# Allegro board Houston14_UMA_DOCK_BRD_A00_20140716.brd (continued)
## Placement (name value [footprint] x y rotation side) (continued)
LI6  DLW21HN900HQ2L_4P  [MURAT_DLW21HN900HQ2L_4P]  305 83.04 0 bottom
LI7  DLW21HN900HQ2L_4P  [MURAT_DLW21HN900HQ2L_4P]  302.97 78.47 0 bottom
LI8  DLW21HN900HQ2L_4P  [MURAT_DLW21HN900HQ2L_4P]  221.88 101.69 90 bottom
LI9  DLW21HN900HQ2L_4P  [MURAT_DLW21HN900HQ2L_4P]  220.1 101.69 90 bottom
LL1  4.7UH_BRC2012T4R7MD_20%  [TAIYO_BRC2012T4R7MD_2P]  271.48 85.41 180 top
LV1  BLM15BB221SN1D_2P  [MURAT_BLM15BB221SN1D_2P]  91.54 98.3 270 bottom
LV3  DLW21HN900HQ2L_4P  [MURAT_DLW21HN900HQ2L_4P]  94.65 107.1 90 top
LV6  DLW21HN900HQ2L_4P  [MURAT_DLW21HN900HQ2L_4P]  86.58 106.26 90 top
LV9  DLW21HN900HQ2L_4P  [MURAT_DLW21HN900HQ2L_4P]  92.02 106.24 90 top
LV12  DLW21HN900HQ2L_4P  [MURAT_DLW21HN900HQ2L_4P]  89.06 107.17 90 top
LV16  BLM15BB470SN1D_2P  [MURAT_BLM15BB470SN1D_2P]  254.29 106.63 90 top
LV17  BLM15BB470SN1D_2P  [MURAT_BLM15BB470SN1D_2P]  258.1 106.63 90 top
LV18  BLM15BB470SN1D_2P  [MURAT_BLM15BB470SN1D_2P]  260.64 106.63 90 top
LV19  BLM15AG121SN1D_L0402_2P  [MURAT_BLM15AG121SN1D_L0402_2P]  264.96 110.39 90 top
LV20  BLM15AG121SN1D_L0402_2P  [MURAT_BLM15AG121SN1D_L0402_2P]  267.25 110.39 90 top
LV22  BLM15PX181SN1D_2P  [MURAT_BLM15PX181SN1D_2P]  153.67 83.78 90 top
LV23  BLM15PX181SN1D_2P  [MURAT_BLM15PX181SN1D_2P]  150.62 83.78 90 top
LV24  BLM15PX181SN1D_2P  [MURAT_BLM15PX181SN1D_2P]  149.55 101.16 0 top
LV25  BLM15PX181SN1D_2P  [MURAT_BLM15PX181SN1D_2P]  169.3 87.24 0 top
LV27  DLW21HN900HQ2L_4P  [MURAT_DLW21HN900HQ2L_4P]  103.82 93.52 0 bottom
LZ1  DLW21HN900HQ2L_4P  [MURAT_DLW21HN900HQ2L_4P]  94.21 96.5 90 bottom
MIC1  SPM1437HM4H-6_6P  [KNOW_SPM1437HM4H-6_6P]  247.88 113.47 270 top
NOREF  -  []  107.65 115.8 0 top
NOREF#2  -  []  157.2 27.94 0 top
NOREF#3  -  []  7.45 98.25 0 top
NOREF#4  -  []  131.35 119.42 0 top
NOREF#5  -  []  114.27 39.75 0 top
NOREF#6  -  []  221.65 115.8 0 top
NOREF#7  -  []  179 47.52 0 top
NOREF#8  -  []  319.3 27 0 top
NOREF#9  -  []  198.22 119.33 0 top
NOREF#10  -  []  237.55 3 0 top
NOREF#11  -  []  283.05 111.64 0 top
NOREF#12  -  []  179 71.32 0 top
NOREF#13  -  []  94.53 12.89 0 top
NOREF#14  -  []  246.48 92.85 0 top
NOREF#15  -  []  85.15 60.4 0 top
NOREF#16  -  []  103.35 -30.1 0 top
NOREF#17  -  []  257.65 29.8 0 top
NOREF#18  -  []  18.5 80.8 0 top
NOREF#19  -  []  158.65 1.5 0 top
NOREF#20  -  []  117.7 47.52 0 top
NOREF#21  -  []  55.05 115.3 0 top
NOREF#22  -  []  117.7 71.32 0 top
NOREF#23  -  []  18.5 80.8 0 top
NOREF#24  -  []  182.09 22.32 0 top
NOREF#25  -  []  59.65 3.15 0 top
NOREF#26  -  []  279.1 74.41 0 top
NOREF#27  -  []  156.12 19.2 0 top
NOREF#28  -  []  170.8 34.69 180 bottom
NOREF#29  -  []  190.93 24.73 180 bottom
NOREF#30  -  []  249.94 46.87 90 bottom
NOREF#31  -  []  181.79 32.65 180 bottom
NOREF#32  -  []  245.29 44.02 180 bottom
PBATT1  DEREN_40-42251-01001RHF  [DEREN_40-42251-01001RHF_10P-T]  77.6 15.08 214.6 bottom
PC1  1U_0603_10V4Z  [C_0603]  308.34 73.31 270 top
PC3  2200P_0402_50V7K  [C_0402]  72.27 11.24 225 top
PC4  1500P_0402_50V7K  [C_0402]  88.05 3.7 270 top
PC5  0.022U_0805_50V7K  [C_0805]  55.41 88.37 90 bottom
PC9  1000P_0603_50V7K  [C_0603]  44.27 86.82 270 bottom
PC10  10U_0805_25V6K  [C_0805]  58.55 94.55 180 bottom
PC20  0.1U_0402_25V6  [C_0402]  54.84 99.29 0 bottom
PC21  10U_0805_25V6K  [C_0805]  45.81 86.76 270 bottom
PC22  10U_0805_25V6K  [C_0805]  53.28 94.25 0 bottom
PC100  4.7U_0603_10V6K  [C_0603]  220 62.87 90 bottom
PC101  10U_0805_25V6K  [C_0805]  208.74 67.12 0 top
PC102  10U_0805_25V6K  [C_0805]  208.74 67.12 0 bottom
PC105  2200P_0402_50V7K  [C_0402]  208.88 65.6 0 top
PC106  0.1U_0402_25V6  [C_0402]  208.85 64.7 0 top
PC109  0.1U_0603_25V7K  [C_0603]  218.73 67.19 90 top
PC110  0.1U_0603_25V7K  [C_0603]  219.06 58.69 90 top
PC111  680P_0603_50V7K  [C_0603]  213.91 70.23 270 top
PC113  220U_6.3V_M  [C_APXK6R3ARA221MF451]  216.7 76.76 270 bottom
PC114  680P_0603_50V7K  [C_0603]  213.94 60.12 90 top
PC115  220U_6.3V_M  [C_APXK6R3ARA221MF451]  216.19 54.75 90 bottom
PC117  0.1U_0603_25V7K  [C_0603]  215.11 64.58 180 top
PC118  4.7U_0603_10V6K  [C_0603]  216.9 64.26 270 bottom
PC119  1U_0603_10V6K  [C_0603]  221.96 66.98 0 top
PC200  10U_0805_25V6K  [C_0805]  244.26 34.95 270 top
PC201  10U_0805_25V6K  [C_0805]  246.04 34.95 270 top
PC203  2200P_0402_50V7K  [C_0402]  242.86 34.69 270 top
PC204  0.22U_0603_16V7K  [C_0603]  253.97 34.99 0 bottom
PC205  22U_0805_6.3V6M  [C_0805]  257.34 40.62 90 bottom
PC206  0.1U_0402_25V6  [C_0402]  241.96 34.69 270 top
PC207  220U_D2_2VY_R17M  [C_D2]  243.99 35.84 270 bottom
PC208  680P_0603_50V7K  [C_0603]  246.61 29.02 180 top
PC209  1U_0603_10V6K  [C_0603]  263.08 32.62 180 bottom
PC211  1U_0603_10V6K  [C_0603]  261.67 33.85 0 bottom
PC212  0.033U_0402_16V7K  [C_0402]  258.99 40.5 90 bottom
PC213  100P_0402_50V8J  [C_0402]  260.97 40.45 180 bottom
PC214  .1U_0402_16V7K  [C_0402]  260.01 42.53 90 bottom
PC215  .1U_0402_16V7K  [C_0402]  262.34 36.01 0 bottom
PC300  2200P_0402_50V7K  [C_0402]  216.98 52.12 180 bottom
PC301  680P_0603_50V7K  [C_0603]  214.16 52.58 270 bottom
PC302  0.1U_0603_25V7K  [C_0603]  218.29 47.97 180 top
PC303  10U_0805_25V6K  [C_0805]  217.68 50.82 180 bottom
PC304  330P_0402_50V7K  [C_0402]  217.26 44.52 0 bottom
PC305  47U_0805_6.3V6M  [C_0805]  203.49 51.03 90 bottom
PC306  47U_0805_6.3V6M  [C_0805]  205.27 51.03 90 bottom
PC307  22U_0805_6.3VAM  [C_0805]  205.27 51.03 90 top
PC308  22U_0805_6.3VAM  [C_0805]  203.49 51.03 90 top
PC309  4.7U_0603_6.3V6K  [C_0603]  219.49 44.45 270 bottom
PC310  4.7U_0603_6.3V6K  [C_0603]  218.8 47.06 0 bottom
PC311  0.1U_0402_25V6  [C_0402]  219.67 48.82 0 bottom
PC400  1U_0402_6.3V6K  [C_0402]  230.42 60.06 90 bottom
PC401  4.7U_0805_6.3V6K  [C_0805]  228.64 60.18 90 bottom
PC402  .1U_0402_16V7K  [C_0402]  232.45 60.06 90 bottom
PC403  0.01U_0402_25V7K  [C_0402]  230.72 50.87 0 bottom
PC404  22U_0805_6.3V6M  [C_0805]  228.94 50.94 270 bottom
PC500  4700P_0603_50V7K  [C_0603]  105.96 76.2 270 bottom
PC501  .1U_0402_16V7K  [C_0402]  107.23 75.05 90 bottom
PC502  0.068U_0402_16V7K  [C_0402]  109 71.49 90 bottom
PC503  1000P_0402_50V7K  [C_0402]  122.47 90.16 90 top
PC504  0.1U_0402_25V6  [C_0402]  130.85 94 270 bottom
PC505  1U_0603_10V6K  [C_0603]  99.16 67.63 0 bottom
PC506  100P_0402_50V8J  [C_0402]  109 67.33 270 bottom
PC507  0.33U_0603_10V7K  [C_0603]  107.73 64.65 90 bottom
PC508  680P_0603_50V7K  [C_0603]  121.07 86.49 90 top
PC509  1U_0603_10V7K  [C_0603]  129.39 87.82 0 top
PC510  1U_0603_10V7K  [C_0603]  106.46 64.65 90 bottom
PC511  0.1U_0402_25V6  [C_0402]  99.86 65.14 90 bottom
PC512  1500P_0402_50V7K  [C_0402]  111.75 65.34 180 bottom
PC513  0.068U_0402_16V7K  [C_0402]  110.02 71.49 90 bottom
PC514  47P_0402_50V8J  [C_0402]  106.29 64.71 180 top
PC515  10U_0805_25V6K  [C_0805]  125.64 91.34 270 top
PC516  10U_0805_25V6K  [C_0805]  125.64 91.34 270 bottom
PC517  10U_0805_25V6K  [C_0805]  123.86 91.34 270 bottom
PC518  10U_0805_25V6K  [C_0805]  123.86 91.34 270 top
PC519  100U_D_20VM_R55M  [C_D]  120.31 93.35 270 bottom
PC520  2200P_0402_50V7K  [C_0402]  121.58 91.07 270 top
PC521  0.1U_0402_25V6  [C_0402]  126.96 91.35 270 top
PC700  0.1U_0603_25V7K  [C_0603]  63.03 90.17 270 top
PC701  1U_0603_25V6K  [C_0603]  80.75 81.09 180 top
PC702  0.1U_0402_25V6  [C_0402]  79.34 82.24 0 top
PC703  0.1U_0402_25V6  [C_0402]  81.19 83.07 270 top
PC704  10U_0805_25V6K  [C_0805]  94.53 78.64 270 top
PC705  10U_0805_25V6K  [C_0805]  96.3 78.64 270 top
PC706  10U_0805_25V6K  [C_0805]  96.3 78.64 270 bottom
PC707  10U_0805_25V6K  [C_0805]  94.53 78.64 270 bottom
PC708  22U_0805_25V6M  [C_0805]  98.08 78.64 270 top
PC709  10U_0805_25V6K  [C_0805]  82.75 80.46 0 top
PC710  1U_0603_10V6K  [C_0603]  82.63 75.95 0 top
PC711  0.1U_0402_25V6  [C_0402]  79.03 79.39 270 bottom
PC712  0.047U_0603_25V7K~D  [C_0603]  84.3 78.96 180 top
PC713  2200P_0402_50V7K  [C_0402]  80.95 85.4 90 bottom
PC714  22U_0805_25V6M  [C_0805]  82.33 84.39 90 bottom
PC715  22U_0805_25V6M  [C_0805]  84.05 84.38 90 top
PC716  22U_0805_25V6M  [C_0805]  82.33 84.39 90 top
PC717  22U_0805_25V6M  [C_0805]  84.05 84.38 90 bottom
PC718  100P_0402_50V8J  [C_0402]  75.98 78.48 90 bottom
PC719  100P_0402_50V8J  [C_0402]  73.49 79.19 0 top
PC721  1000P_0603_50V7K  [C_0603]  89.79 89.96 270 bottom
PC722  0.1U_0603_25V7K  [C_0603]  113.83 83.95 90 top
PC723  10U_0805_25V6K  [C_0805]  114.08 84.05 90 bottom
PC724  10U_0805_25V6K  [C_0805]  112.05 84.05 90 top
PC725  10U_0805_25V6K  [C_0805]  112.05 84.05 90 bottom
PC726  0.1U_0402_25V6  [C_0402]  82.33 71.11 90 bottom
PC727  0.1U_0402_25V6  [C_0402]  82.28 73.6 180 bottom
PC728  0.1U_0402_25V6  [C_0402]  81.32 72.02 270 bottom
PC729  1U_0603_25V6K  [C_0603]  79.16 72.14 270 bottom
PC732  0.1U_0402_25V6  [C_0402]  80.06 85.54 90 bottom
PC737  100P_0402_50V8J  [C_0402]  74.41 75.14 180 top
PC741  100P_0402_50V8J  [C_0402]  76.9 73.85 180 top
PC805  0.1U_0402_10V7K  [C_0402]  68.99 81.93 180 bottom
PC807  0.47U_0805_25V6K  [C_0805]  117.3 98.19 0 top
PC809  1500P_0402_50V7K  [C_0402]  133.64 103.77 270 top
PC810  0.1U_0402_10V7K  [C_0402]  93.38 71.62 90 top
PC813  0.1U_0603_50V4Z  [C_0603]  99.35 61.98 90 bottom
PC815  0.1U_0603_25V7K  [C_0603]  100.57 62 90 bottom
PC816  0.047U_0603_25V7M  [C_0603]  107.29 59.12 0 bottom
PC817  0.1U_0402_25V4Z~D  [C_0402]  107.21 58.08 0 bottom
PC900  22U_0805_6.3V6M  [C_0805]  148.02 77.26 90 bottom
PC901  22U_0805_6.3V6M  [C_0805]  143.23 77.21 90 bottom
PC902  22U_0805_6.3V6M  [C_0805]  140.5 77.19 90 bottom
PC903  22U_0805_6.3V6M  [C_0805]  137.96 77.19 90 bottom
PC904  22U_0805_6.3V6M  [C_0805]  132.88 77.19 90 bottom
PC913  22U_0805_6.3V6M  [C_0805]  145.85 77.21 90 bottom
PC914  22U_0805_6.3V6M  [C_0805]  135.45 77.16 90 bottom
PC915  2.2U_0805_10V6K  [C_0805]  138.04 77.33 90 top
PC916  2.2U_0805_10V6K  [C_0805]  143.4 77.33 90 top
PC917  22U_0805_6.3V6M  [C_0805]  140.5 77.33 90 top
PC966  220U 2.5V Y D2 ESR9M H1.9 SX  [C_D2]  133.68 81.8 0 bottom
PD1  -  [TVNST52302AB0_SOT523-3]  74.23 7.9 225 top
PD2  -  [TVNST52302AB0_SOT523-3]  72.72 6.43 225 top
PD3  BAS40CW SOT-323  [BAS40-05W_SC70-3]  309.45 72.61 90 top
PD4  SDMK0340L-7-F_SOD323-2~D  [RB751V-40_SOD323-2]  71.11 4.94 270 top
PD5  -  [AZC199-02SPR7G_SOT23-3]  57.43 82.27 270 bottom
PD702  SDMK0340L-7-F_SOD323-2~D  [SDMK0340L-7-F_SOD323-2]  94.6 61.79 0 top
PD704  SDMK0340L-7-F_SOD323-2~D  [SDMK0340L-7-F_SOD323-2]  94.6 60.06 0 top
PD705  SDMK0340L-7-F_SOD323-2~D  [SDMK0340L-7-F_SOD323-2]  94.6 58.31 0 top
PD800  -  [PDS5100H-13_POWERDI5-3]  110.67 80.58 0 top
PD808  -  [PDS5100H-13_POWERDI5-3]  118.42 103 0 bottom
PD813  SDMK0340L-7-F_SOD323-2~D  [SDMK0340L-7-F_SOD323-2]  133.7 101.29 180 top
PD815  -  [BAT54CW_SOT323-3]  54.76 94.81 90 top
PD817  -  [BAT54CW_SOT323-3]  95.78 70.85 0 bottom
PH500  100K_0402_1%_NCP15WF104F03RC  [R_0402]  131.86 90.44 270 bottom
PH501  10K_0402_1%_TSM0A103F34D1RZ  [R_0402]  123.18 75.89 180 bottom
PJP1  PAD-OPEN 1x3m  [JUMP_43X118]  40.73 86.67 270 bottom
PJP4  PAD-OPEN1x1m  [JUMP_43X39]  294.42 38.06 270 bottom
PJP5  PAD-OPEN1x1m  [JUMP_43X39]  294.47 33.17 180 bottom
PJP6  PAD-OPEN1x2m  [JUMP_43X79]  26.97 98.01 0 bottom
PJP7  PAD-OPEN1x1m  [JUMP_43X39]  304.93 49.05 0 top
PJP9  PAD-OPEN1X2m  [JUMP_43X79]  35.66 83.59 270 bottom
PJP10  PAD-OPEN1x1m  [JUMP_43X39]  33.3 94.62 180 bottom
PJP11  PAD-OPEN1x1m  [JUMP_43X39]  195.36 55.49 90 top
PJP12  PAD-OPEN1x1m  [JUMP_43X39]  277.91 56.5 90 top
PJP13  PAD-OPEN1x2m  [JUMP_43X79]  273.41 75.25 90 top
PJP14  PAD-OPEN1x1m  [JUMP_43X39]  245.07 85.79 0 top
PJP15  PAD-OPEN1x1m  [JUMP_43X39]  245.45 64.07 0 top
PJP16  PAD-OPEN1x1m  [JUMP_43X39]  237.22 31.82 180 top
PJP17  PAD-OPEN1x1m  [JUMP_43X39]  271.31 56.5 90 top
PJP18  PAD-OPEN1x3m  [JUMP_43X118]  183.64 79.82 0 top
PJP20  PAD-OPEN1x1m  [JUMP_43X39]  188.95 38.98 90 top
PJP21  PAD-OPEN1x3m  [JUMP_43X118]  212.13 93.45 270 top
PJP22  PAD-OPEN1x3m  [JUMP_43X118]  221.65 92.35 90 top
PJP23  PAD-OPEN1x1m  [JUMP_43X39]  156.32 39.82 180 top
PJP24  PAD-OPEN1x1m  [JUMP_43X39]  150.71 79.9 90 top
PJP25  PAD-OPEN1x1m  [JUMP_43X39]  173.72 88.97 180 top
PJP26  PAD-OPEN1x2m  [JUMP_43X79]  307.34 53.78 90 top
PJP29  PAD-OPEN1x1m  [JUMP_43X39]  85.38 98.06 270 top
PJP32  PAD-OPEN1x1m  [JUMP_43X39]  266.41 77.78 270 top
PJP35  PAD-OPEN1x1m  [JUMP_43X39]  168.4 78.23 270 top
PJP36  PAD-OPEN1x3m  [JUMP_43X118]  177.11 85.99 90 top
PJP100  PAD-OPEN 1x3m  [JUMP_43X118]  203.82 69.04 270 bottom
PJP101  PAD-OPEN 1x3m  [JUMP_43X118]  220.98 55.95 0 bottom
PJP102  PAD-OPEN 1x3m  [JUMP_43X118]  222.86 75.78 90 bottom
PJP200  PAD-OPEN 1x2m~D  [JUMP_43X79]  244.13 38.97 270 top
PJP201  PAD-OPEN1x1m  [JUMP_43X39]  254.8 38.22 90 bottom
PJP202  PAD-OPEN1x1m  [JUMP_43X39]  255.26 41.21 180 bottom
PJP203  JUMP_1x3m  [JUMP_43X118]  238.29 26.52 270 bottom
PJP204  JUMP_1x3m  [JUMP_43X118]  236.05 32.32 180 bottom
PJP300  -  [JUMP_43X118]  203.53 47.82 180 bottom
PJP302  PAD-OPEN 1x2m~D  [JUMP_43X79]  220.51 51.18 180 bottom
PJP400  PAD-OPEN1x1m  [JUMP_43X39]  225.89 61.03 0 bottom
PJP401  PAD-OPEN1x1m  [JUMP_43X39]  226.73 50.94 270 bottom
PJP500  PAD-OPEN 4x4m  [JUMP_43X118]  112.81 90.58 90 bottom
PJP700  PAD-OPEN 4x4m  [JUMP_43X118-NPM]  71.54 95.74 270 bottom
PJP701  PAD-OPEN1x1m  [JUMP_43X39]  78.83 68.39 0 top
PJPDC1  CVILU_CI0805M1HRC-NH  [CVILU_CI0805M1HRC-NH_5P-T]  48.63 89.73 180 bottom
PL1  FBMJ4516HS720NT_2P  [TAIYO_FBMJ4516HS720NT_2P]  75.41 10.41 90 top
PL2  FBMJ4516HS720NT_2P  [TAIYO_FBMJ4516HS720NT_2P]  77.8 12 90 top
PL3  BLM15AG102SN1D_2P  [MURAT_BLM15AG102SN1D_2P]  55.38 84.74 180 bottom
PL4  FBMJ4516HS720NT_2P  [TAIYO_FBMJ4516HS720NT_2P]  48.53 86.82 0 bottom
PL100  1UH +-20% 6.6A  [L_5X5X3_M_2P-NPM]  203.97 70.37 270 bottom
PL101  2.2UH_7.8A_20%  [PANAS_ETQP3W2R2WFN_2P]  209.72 77.39 90 bottom
PL102  3.3UH_6.3A_20%  [PANAS_ETQP3W2R2WFN_2P]  208.95 61.13 90 bottom
PL200  1UH_11A_20%  [PANAS_ETQP3W2R2WFN_2P]  249.85 35.91 90 bottom
PL301  0.68UH +-20% 7.9A  [L_5X5X3_M_2P]  211.88 47.84 180 bottom
PL500  0.15UH_PCME064T-R15MS0R667_36A_20%  [PANAS_ETQP4LR15AFM_4P]  128.24 81.85 180 bottom
PL501  FBMA-L11-453215800LMA90T_2P  [FBMA-L11-453215800LMA90T_2P-NPM]  112.81 89.12 90 bottom
PL700  1UH +-20% 6.6A  [L_5X5X3_M_2P]  71.54 93.39 90 bottom
PL701  3.3UH_10A_20%  [TOKO_FDVE1040-H-3R3M-P3_2P]  103.35 84.9 180 bottom
PQ1  DMG2301U-7 1P SOT23-3  [SI2301CDS-T1-GE3_SOT23-3]  84.21 4.13 270 top
PQ2  -  [FDV301N-G_SOT23-3]  46.94 80.98 270 bottom
PQ3  MMST3904-7-F_SOT323~D  [MMST3904-7-F_SOT323-3]  50.84 79.63 180 bottom
PQ4  -  [FDMC6679AZ_MLP8-5]  57.79 90.64 90 bottom
PQ6  DCX124EK-7-F PNP/NPN_SC74-6~D  [IMD2AT-108_SC74-6]  59.99 85.6 270 bottom
PQ100  -  [SIS412DN-T1-GE3_POWERPAK8-5]  208.35 72.76 180 top
PQ101  -  [SIS412DN-T1-GE3_POWERPAK8-5]  206.6 60.34 0 top
PQ102  -  [SI7716ADN-T1-GE3_POWERPAK8-5]  210.18 69.89 0 top
PQ103  -  [SI7716ADN-T1-GE3_POWERPAK8-5]  212.27 63.21 180 top
PQ200  -  [SIS412DN-T1-GE3_POWERPAK8-5]  250.9 35.91 90 top
PQ201  -  [SI7716ADN-T1-GE3_POWERPAK8-5]  248.03 34.08 270 top
PQ700  -  [SI4835DDY-T1-GE3_SO8]  65.7 93.56 180 bottom
PQ701  -  [NTR4502PT1G_SOT23-3]  69.89 90.26 180 top
PQ702  -  [NTR4502PT1G_SOT23-3]  65.82 90.26 180 top
PQ703  SI3993CDV-T1-GE3_TSOP6  [NTGD4161PT1G_TSOP6]  176.89 115.48 0 top
PQ705  -  [AON6970_DFN5X6D-8-7]  89.7 81.5 180 bottom
PQ800  -  [SI4835DDY-T1-GE3_SO8]  109.16 78.68 90 bottom
PQ806  -  [DMN65D8LDW-7_SOT363-6]  64.57 79.2 270 bottom
PQ810  -  [FDS6679AZ-G_SO8]  118.78 96.21 90 bottom
PQ813  -  [DMN65D8LDW-7_SOT363-6]  88.58 66.22 90 bottom
PQ814  -  [NTR4502PT1G_SOT23-3]  97.35 67.38 270 bottom
PQ815  -  [FDS6679AZ-G_SO8]  128.31 103.58 0 bottom
PQ816  -  [DMN65D8LW-7_SOT323-3]  132.12 95.34 180 top
PQ817  -  [DMN65D8LDW-7_SOT363-6]  88.66 73.37 90 bottom
PQ826  -  [FDMC6679AZ_MLP8-5]  132.97 105.35 180 bottom
PQ829  DMG2301U-7 1P SOT23-3  [SI2301CDS-T1-GE3_SOT23-3]  55.46 91.51 90 top
PQ832  -  [DMN65D8LW-7_SOT323-3]  50.55 94.81 90 top
PR1  1K_0402_5%  [R_0402]  312.41 72.81 270 top
PR2  100K_0402_5%  [R_0402]  72.4 4.03 90 top
PR6  0_0402_5%  [R0402_0OHM]  88.18 5.48 270 top
PR7  0_0402_5%  [R_0402]  46.98 83.63 180 bottom
PR8  2.2K_0402_5%  [R_0402]  42.96 82.92 90 bottom
PR9  33_0402_5%  [R_0402]  44.95 83.63 180 bottom
PR10  100K_0402_1%  [R_0402]  49.01 82.62 180 bottom
PR11  10K_0402_1%  [R_0402]  42.96 80.79 270 bottom
PR12  15K_0402_1%  [R_0402]  50.08 83.58 270 bottom
PR13  10K_0402_5%  [R_0402]  48.81 79.62 90 bottom
PR14  1M_0402_5%  [R_0402]  58.66 88.46 180 top
PR15  100K_0402_5%  [R_0402]  60.06 99.25 180 bottom
PR16  4.7K_0805_5%  [R_0805]  57.86 90.74 0 top
PR17  10K_0402_5%  [R_0402]  56.68 87.39 270 top
PR18  1M_0402_5%  [R_0402]  57.7 87.39 270 top
PR100  6.49K_0402_1%  [R_0402]  222.75 64.84 180 bottom
PR101  15K_0402_1%  [R_0402]  221.83 62.8 0 bottom
PR102  10K_0402_1%  [R_0402]  222.75 64.84 180 top
PR103  0_0402_5%  [R0402_0OHM]  222.75 63.82 180 top
PR104  10K_0402_1%  [R_0402]  221.83 62.8 0 top
PR105  20K_0402_1%  [R_0402]  222.75 65.85 180 top
PR106  16.9K_0402_1%  [R_0402]  222.75 61.79 180 top
PR107  100K_0402_1%  [R_0402]  221.02 67.43 90 top
PR108  0_0402_5%  [R0402_0OHM]  220 68.34 270 top
PR109  2.2_0603_5%  [R_0603]  217.82 60.09 270 top
PR110  2.2_0603_5%  [R_0603]  217.46 68.58 270 top
PR111  4.7_1206_5%  [R_1206]  210.79 74.49 0 top
PR112  4.7_1206_5%  [R_1206]  211.21 58.28 0 top
PR113  0_0402_5%  [R0402_0OHM]  223 67.12 180 bottom
PR114  200_0402_1%  [R_0402]  220.16 59.94 270 top
PR200  2.2_0603_5%  [R_0603]  253.59 36.9 0 bottom
PR201  19.6K_0402_1%  [R_0402]  260.08 35.63 180 top
PR202  5.1_0603_5%  [R_0603]  263.07 33.85 180 top
PR203  4.7_1206_5%  [R_1206]  250.67 29.78 180 top
PR204  0_0603_5%  [R0603_0OHM]  261.67 32.62 0 top
PR205  8.06K_0402_1%  [R_0402]  260.97 41.47 180 bottom
PR206  768K_0402_1%  [R_0402]  263.26 35.12 180 bottom
PR207  0_0402_5%  [R0402_0OHM]  263.26 38.04 180 bottom
PR209  10K_0402_1%  [R_0402]  261.02 42.53 90 bottom
PR210  0_0402_5%  [R0402_0OHM]  263.26 40.07 180 bottom
PR303  1M_0402_1%  [R_0402]  214.11 44.77 180 bottom
PR305  4.7_1206_5%  [R_1206]  210.03 52.14 0 bottom
PR306  0_0402_5%  [R_0402]  215.18 43.55 90 bottom
PR307  7.5K_0402_1%  [R_0402]  217.26 43.5 0 bottom
PR308  0_0402_5%  [R_0402]  216.19 44.47 270 bottom
PR309  1K_0402_5%  [R_0402]  218.17 44.45 180 top
PR310  10K_0402_1%  [R_0402]  218.17 43.5 180 top
PR312  0_0603_5%  [R0603_0OHM]  215.73 47.98 180 top
PR313  0_0402_5%  [R0402_0OHM]  214.27 43.73 90 top
PR315  100K_0402_1%  [R_0402]  215.18 43.74 90 top
PR400  100K_0402_5%  [R_0402]  233.46 60.98 270 bottom
PR401  47K_0402_5%  [R_0402]  231.43 60.06 90 bottom
PR402  8.66K_0402_1%  [R_0402]  230.72 49.85 0 bottom
PR403  10K_0402_1%  [R_0402]  232.7 50.82 270 bottom
PR500  75_0402_1%  [R_0402]  108.24 75.05 90 bottom
PR501  365K_0402_1%  [R_0402]  104.69 75.05 90 bottom
PR502  75_0402_1%  [R_0402]  103.67 75.05 90 bottom
PR503  681K_0402_1%  [R_0402]  102.65 75.05 90 bottom
PR504  36.5K_0402_1%  [R_0402]  101.64 75.05 90 bottom
PR505  10K_0402_5%  [R_0402]  106.46 71.87 90 top
PR506  39K_0402_1%  [R_0402]  105.45 71.87 90 top
PR507  150K_0402_1%  [R_0402]  104.43 71.87 90 top
PR508  100K_0402_1%  [R_0402]  103.42 71.87 90 top
PR509  20K_0402_1%  [R_0402]  102.4 71.87 90 top
PR510  39K_0402_5%~N  [R_0402]  107.48 71.87 90 top
PR511  10K_0402_5%  [R_0402]  109.26 75.96 270 bottom
PR512  2.15K_0402_1%  [R_0402]  122.26 77.28 0 bottom
PR513  75_0402_1%  [R_0402]  100.32 72.2 180 bottom
PR514  20K_0402_1%  [R_0402]  124.96 77.28 180 bottom
PR515  3.01K_0402_1%  [R_0402]  124.96 75.89 180 bottom
PR516  1.91K_0402_1%  [R_0402]  100.32 70.17 180 bottom
PR517  2.2_0603_5%  [R_0603]  129.58 93.09 90 bottom
PR518  2M_0402_1%  [R_0402]  107.77 74.92 180 top
PR519  1_0603_5%  [R_0603]  99.16 68.9 0 bottom
PR520  0_0402_5%  [R0402_0OHM]  99.4 73.22 0 bottom
PR521  4.87K_0402_1%  [R_0402]  109.97 65.34 180 bottom
PR522  4.7_1206_5%  [R_1206]  125.2 87.06 180 top
PR523  10K_0402_5%  [R_0402]  110.02 67.33 270 bottom
PR524  2M_0402_1%  [R_0402]  105.55 74.79 180 top
PR525  27K_0402_1%  [R_0402]  106.86 75.83 0 top
PR526  10_0603_1%  [R_0603]  105.19 66.04 270 bottom
PR527  54.9_0402_1%  [R_0402]  102.91 65.14 90 bottom
PR528  75_0402_1%  [R_0402]  101.89 65.14 90 bottom
PR529  110_0402_1%  [R_0402]  100.88 65.14 90 bottom
PR531  0_0402_5%  [R0402_0OHM]  109.97 68.39 180 bottom
PR532  0_0402_5%  [R0402_0OHM]  109.97 69.41 180 bottom
PR534  0_0402_5%  [R0402_0OHM]  103.92 65.14 90 bottom
PR535  4.75K_0402_1%  [R_0402]  111.04 67.33 270 bottom
PR536  0_0402_5%  [R0402_0OHM]  99.4 74.23 0 bottom
PR539  0_0402_5%  [R0402_0OHM]  100.32 71.19 180 bottom
PR700  0_0402_5%  [R0402_0OHM]  62.01 91.46 270 bottom
PR701  0.01_1206_1%  [R_1206_4P-D]  67.6 98.58 270 bottom
PR702  0_0402_5%  [R0402_0OHM]  63.03 86.73 90 top
PR703  100_0402_1%  [R_0402]  80.18 83.23 180 bottom
PR704  0_0402_5%  [R0402_0OHM]  79.29 84.09 270 top
PR705  0_0402_5%  [R0402_0OHM]  80.3 84.09 270 top
PR706  100K_0402_1%  [R_0402]  175.43 118.89 270 top
PR707  100K_0402_1%  [R_0402]  175.43 115.81 90 top
PR708  10_1206_5%  [R_1206]  85.19 82.49 180 top
PR709  0_0402_5%  [R0402_0OHM]  174.41 115.81 90 top
PR710  34K_0402_1%  [R_0402]  77.3 81.35 0 bottom
PR711  6.49K_0402_1%  [R_0402]  78.02 79.39 270 bottom
PR712  2.2_0603_5%  [R_0603]  82.63 77.18 0 top
PR713  100K_0402_1%  [R_0402]  76.8 83.25 0 top
PR714  0_0402_5%  [R0402_0OHM]  77.76 82.18 270 top
PR715  154K_0402_1%  [R_0402]  77 79.39 270 bottom
PR716  0_0402_5%  [R0402_0OHM]  76.75 82.18 270 top
PR717  0_0402_5%  [R0402_0OHM]  73.49 76.14 0 top
PR718  0_0402_5%  [R0402_0OHM]  73.49 80.2 0 top
PR720  0_0402_5%  [R0402_0OHM]  73.49 77.16 0 top
PR721  0.01_1206_1%  [R_1206_4P-D]  105.41 78.3 180 bottom
PR722  4.02K_0402_1%  [R_0402]  80.3 72.02 270 bottom
PR723  10_0603_1%  [R_0603]  77.89 72.14 270 bottom
PR725  1K_0402_5%  [R_0402]  78.27 71.11 90 top
PR726  4.7_1206_5%  [R_1206]  91.48 91.44 270 bottom
PR728  0_0402_5%  [R0402_0OHM]  76.24 71.11 90 top
PR729  154K_0402_1%  [R_0402]  77.25 72.02 270 top
PR737  649K_0402_1%  [R_0402]  107.28 52.9 0 bottom
PR738  3M_0402_5%  [R_0402]  109.13 52.09 270 bottom
PR740  10K_0402_1%  [R_0402]  110.15 51.17 90 bottom
PR743  0_0402_5%  [R0402_0OHM]  111.04 51.17 90 bottom
PR745  100K_0402_1%  [R_0402]  108.19 52.01 180 bottom
PR788  20K_0402_1%  [R_0402]  73.49 78.16 0 top
PR799  10K_0402_1%  [R_0402]  82.54 74.84 0 top
PR810  100K_0402_5%  [R_0402]  69.52 78.13 270 bottom
PR811  0_0402_5%  [R0402_0OHM]  119.11 99.89 180 top
PR812  0_0402_5%  [R0402_0OHM]  64.08 76.79 0 bottom
PR813  100K_0402_5%  [R_0402]  102.91 43.17 90 bottom
PR814  330K_0402_5%  [R_0402]  123.56 99.68 0 top
PR815  100K_0402_5%  [R_0402]  102.73 40.83 180 bottom
PR816  0_0402_5%  [R_0402]  106.72 43.55 90 top
PR818  100K_0402_5%  [R_0402]  132.63 102.86 90 top
PR819  100K_0402_5%  [R_0402]  93.51 75.71 270 top
PR822  10K_0402_5%  [R_0402]  133.88 97.67 270 top
PR826  100K_0402_5%  [R_0402]  92.49 65.14 90 bottom
PR827  100K_0402_5%  [R_0402]  93.51 65.14 90 bottom
PR828  10K_0402_5%  [R_0402]  55.61 86.68 180 bottom
PR829  100K_0402_5%  [R_0402]  85.69 66.87 0 bottom
PR830  100K_0402_5%  [R_0402]  51.12 91.56 90 top
PR831  100_0603_1%  [R_0603]  96.43 59.88 0 bottom
PR832  100_0603_1%  [R_0603]  96.56 58.61 180 bottom
PR835  47_0805_5%~D  [R_0805]  97.83 63.78 270 bottom
PR838  100_0603_1%  [R_0603]  97.8 55.16 180 bottom
PR842  0_0402_5%  [R0402_0OHM]  101.63 62.93 270 bottom
PR843  0_0402_5%  [R0402_0OHM]  99.1 52.34 270 bottom
PR844  10K_0402_5%  [R_0402]  53.66 94.6 90 top
PR845  0_0402_5%  [R0402_0OHM]  100.11 52.34 270 bottom
PR846  100K_0402_5%  [R_0402]  103.37 65.34 180 top
PR847  100_0603_1%  [R_0603]  102.68 63.17 270 bottom
PR848  0_0402_5%  [R0402_0OHM]  101.13 52.34 270 bottom
PR850  0_0402_5%  [R0402_0OHM]  103.16 52.34 270 bottom
PR851  0_0402_5%  [R0402_0OHM]  103.92 62.88 270 bottom
PR853  0_0402_5%  [R0402_0OHM]  92.49 68.09 270 bottom
PR854  0_0402_5%  [R0402_0OHM]  104.43 52.34 270 bottom
PR855  0_0402_5%  [R0402_0OHM]  104.94 62.88 270 bottom
PR857  0_0402_5%  [R0402_0OHM]  107.28 54.8 0 bottom
PR858  1M_0402_5%  [R_0402]  102.15 51.42 90 bottom
PR859  0_0402_5%  [R0402_0OHM]  107.28 53.79 0 bottom
PR860  100_0603_1%  [R_0603]  107.12 57 0 bottom
PR863  0_0402_5%  [R_0402]  105.7 52.34 270 bottom
PR864  100K_0402_5%  [R_0402]  93.56 73.73 0 top
PR874  1M_0402_5%  [R_0402]  107.28 55.72 0 bottom
PR895  0_0402_5%  [R0402_0OHM]  50.41 90.49 0 top
PRP2  100_0804_8P4R_5%  [RP_0804_8P4R]  74.86 4.79 135 top
PT1  PAD~D  [TPC12]  244.2 53.49 180 bottom
PT2  PAD~D  [TPC12]  245.82 55.67 180 bottom
PU1  TS5A63157DCKR_SC70-6~D  [TS5A63157DCKR_SC70-6]  40.6 82.3 0 bottom
PU100  -  [TPS51285BRUKR_QFN20_3X3]  219.91 63.05 90 top
PU200  -  [RT8207MZQW_WQFN20_3X3]  258.06 38.57 0 bottom
PU300  SYX198DQNC_QFN10_3X3  [SY8208DQNC_QFN10_3X3]  214.92 46.33 0 bottom
PU400  -  [APL5930KAI-TRG_SO8]  233.08 52.86 180 bottom
PU500  TPS51624RSM_QFN32_4X4  [TPS51622RSM_QFN32_4X4]  102.57 69.34 90 bottom
PU501  -  [CSD97374CQ4M_SON8_3P5X4P5]  130.54 87.72 180 bottom
PU700  BQ24777RUYR_WQFN28_4x4  [BQ24715URUYR_WQFN28_4X4]  79.72 79.46 270 top
PU800  CD3301BRHHR_QFN36_6X6~D  [CD3301RHHR_QFN36_6X6]  100.4 60.12 0 bottom
PU804  TC7SH08FU_SSOP5~D  [TC7SH08FU_SSOP5]  68.27 78.15 270 bottom
PU806  TC7SH08FU_SSOP5~D  [TC7SH08FU_SSOP5]  90.59 72.06 270 bottom
QA1  -  [L2N7002WT1G_SC-70-3]  33.21 100.68 180 top
QA2  -  [DMN66D0LDW-7_SOT363-6]  12.02 94.49 270 top
QA3  -  [DMN66D0LDW-7_SOT363-6]  34.56 95.48 90 bottom
QC1  -  [DMN66D0LDW-7_SOT363-6]  177.52 63.42 90 top
QD1  -  [L2N7002WT1G_SC-70-3]  137.72 3.69 270 top
QE2  -  [DMN66D0LDW-7_SOT363-6]  261.26 67.44 0 top
QE3  MMBT3904WT1G_SC70-3~D  [MMBT3904WT1G_SC70-3]  144.12 59.25 270 top
QE4  MMBT3904WT1G_SC70-3~D  [MMBT3904WT1G_SC70-3]  250.92 67.38 90 top
QE5  MMBT3904WT1G_SC70-3~D  [MMBT3904WT1G_SC70-3]  239.56 9.53 180 bottom
QE6  MMBT3904WT1G_SC70-3~D  [MMBT3904WT1G_SC70-3]  95.03 66.43 0 top
QE7  MMBT3904WT1G_SC70-3~D  [MMBT3904WT1G_SC70-3]  293.31 44.07 180 bottom
QL1  -  [DMN66D0LDW-7_SOT363-6]  251.74 98.05 0 top
QL2  -  [DMN66D0LDW-7_SOT363-6]  237.84 102.29 90 top
QN1  -  [DMN66D0LDW-7_SOT363-6]  281.15 59.11 90 top
QV1  -  [AO6405_TSOP6]  90.43 96.58 270 top
QV2  -  [L2N7002WT1G_SC-70-3]  87.92 93.1 180 top
QV3  -  [DMN66D0LDW-7_SOT363-6]  101.12 105.8 0 top
QV4  -  [L2N7002WT1G_SC-70-3]  83.05 104.9 0 top
QV5  -  [L2N7002WT1G_SC-70-3]  100.62 101.6 0 top
QV7  -  [L2N7002WT1G_SC-70-3]  109.92 101.12 180 bottom
QV8  -  [LP2301ALT1G_SOT23-3]  105.21 97.55 0 bottom
QV9  -  [L2N7002WT1G_SC-70-3]  196.38 103.23 0 bottom
QV10  -  [L2N7002WT1G_SC-70-3]  182.92 103.31 0 bottom
QV11  -  [L2N7002WT1G_SC-70-3]  134.88 86.35 270 bottom
QV20  -  [SI3456DDV-T1-GE3_TSOP6]  166.13 86.59 180 top
QV21  -  [DMN66D0LDW-7_SOT363-6]  169.37 86.09 270 top
QZ1  -  [LP2301ALT1G_SOT23-3]  95.82 99.1 0 top
QZ2  -  [DMN66D0LDW-7_SOT363-6]  275.01 53.09 180 top
QZ3  -  [DMN66D0LDW-7_SOT363-6]  254.15 90.05 0 top
QZ4  -  [DDTA114EUA-7-F_SOT323-3]  249.81 92.65 270 top
QZ6  -  [SI3456DDV-T1-GE3_TSOP6]  174.99 78.36 90 top
QZ7  -  [DMN66D0LDW-7_SOT363-6]  309.01 86.92 0 bottom
QZ9  -  [DDTA114EUA-7-F_SOT323-3]  305.69 85.03 90 bottom
QZ10  -  [DMN66D0LDW-7_SOT363-6]  176.38 84.03 270 top
QZ11  -  [DMN66D0LDW-7_SOT363-6]  278.56 53.09 180 top
R6  10_0402_5%  [R_0402]  165.9 106.44 270 bottom
R41  10_0402_5%  [R_0402]  168.95 106.44 270 bottom
R252  33_0402_5%  [R_0402]  148.63 105.53 90 bottom
R253  33_0402_5%  [R_0402]  149.64 105.53 90 bottom
R254  33_0402_5%  [R_0402]  148.88 119.9 270 top
R255  33_0402_5%  [R_0402]  150.66 105.53 90 bottom
R256  33_0402_5%  [R_0402]  149.9 119.9 270 top
R257  33_0402_5%  [R_0402]  151.68 105.53 90 bottom
R258  33_0402_5%  [R_0402]  152.95 119.9 270 top
R259  33_0402_5%  [R_0402]  147.61 105.53 90 bottom
R260  33_0402_5%  [R_0402]  146.85 119.9 270 top
R261  33_0402_5%  [R_0402]  147.87 119.9 270 top
R262  33_0402_5%  [R_0402]  150.91 119.9 270 top
R263  33_0402_5%  [R_0402]  152.69 105.53 90 bottom
R264  33_0402_5%  [R_0402]  151.93 119.9 270 top
R265  33_0402_5%  [R_0402]  153.71 105.53 90 bottom
R266  33_0402_5%  [R_0402]  154.72 105.53 90 bottom
R267  33_0402_5%  [R_0402]  153.96 119.9 270 top
R268  100K_0402_5%  [R_0402]  157.54 105.41 180 bottom
R271  100K_0402_5%  [R_0402]  156.5 118.63 270 top
R272  100K_0402_5%  [R_0402]  87.36 74.02 270 bottom
R273  10_0402_5%  [R_0402]  178.09 106.44 270 bottom
RA1  10K_0402_5%  [R_0402]  19.25 86.92 90 bottom
RA2  100K_0402_5%  [R_0402]  12.14 97.09 0 top
RA3  0_0603_5%  [R0603_0OHM]  23.15 87.51 90 top
RA4  0_0603_5%  [R0603_0OHM]  21.88 86.85 90 bottom
RA5  2.2K_0402_5%  [R_0402]  21.58 96.59 180 top
RA6  2.2K_0402_5%  [R_0402]  21.58 95.57 180 top
RA7  24.9_0402_1%  [R_0402]  18.53 94.81 180 top
RA8  24.9_0402_1%  [R_0402]  18.53 95.82 180 top
RA9  33_0402_5%  [R_0402]  34.28 97.6 180 top
RA12  1K_0402_5%  [R_0402]  35.9 98.87 0 top
RA13  1K_0402_5%  [R_0402]  35.9 99.89 0 top
RA14  33_0402_5%  [R_0402]  33.36 93.03 0 top
RA17  33_0402_5%  [R_0402]  33.36 94.94 0 top
RA18  10K_0402_5%  [R_0402]  29.76 88 90 top
RA21  100K_0402_5%  [R_0402]  31.97 90.31 90 bottom
RA24  4.7K_0402_5%  [R_0402]  20.87 93.67 90 bottom
RA25  4.7K_0402_5%  [R_0402]  22.31 91.2 90 bottom
RA26  100K_0402_5%  [R_0402]  36.04 94.45 0 bottom
RA27  200K_0402_5%  [R_0402]  32.73 96.27 90 bottom
RA28  100K_0402_5%  [R_0402]  31.84 96.27 90 bottom
RA29  100K_0402_5%  [R_0402]  33.62 96.27 90 bottom
RA30  22_0402_5%  [R_0402]  31.51 102.44 270 top
RA31  22_0402_5%  [R_0402]  30.63 102.44 270 top
RA32  33_0402_5%  [R_0402]  29.73 102.43 270 top
RA35  0_0402_5%  [R0402_0OHM]  27.66 101.32 90 bottom
RA36  0_0402_5%  [R0402_0OHM]  25.39 96.71 270 bottom
RA37  0_0402_5%  [R0402_0OHM]  25.39 97.55 90 bottom
RA38  100K_0402_5%  [R_0402]  28.54 101.32 90 bottom
RA39  0_0805_5%  [R0805_0OHM]  23.57 93.54 0 bottom
RA40  33_0402_5%  [R_0402]  33.36 94.05 0 top
RA44  100K_0402_5%  [R_0402]  25.59 99.75 90 top
RA45  0_0402_5%  [R0402_0OHM]  25.39 99.74 90 bottom
RC1  330K_0402_5%  [R_0402]  169.72 40.25 90 bottom
RC2  1K_0402_5%  [R_0402]  227.95 75.49 0 bottom
RC4  0_0402_5%  [R0402_0OHM]  185.46 45.48 270 bottom
RC7  10M_0402_5%  [R_0402]  186.47 44.47 270 bottom
RC8  20K_0402_5%  [R_0402]  172.77 40.25 90 bottom
RC9  1M_0402_5%  [R_0402]  173.77 40.25 90 bottom
RC10  20K_0402_5%  [R_0402]  171.75 40.25 90 bottom
RC11  1K_0402_5%  [R_0402]  164.86 40.25 90 bottom
RC14  51_0402_5%  [R_0402]  117.59 54.42 180 bottom
RC15  51_0402_5%  [R_0402]  120.64 54.42 180 top
RC16  51_0402_5%  [R_0402]  117.59 55.44 180 bottom
RC17  3.01K_0402_1%  [R_0402]  162.57 77.02 90 bottom
RC18  1K_0402_1%  [R_0402]  117.59 56.45 180 bottom
RC19  33_0402_5%  [R_0402]  165.75 40.25 90 bottom
RC20  33_0402_5%  [R_0402]  163.06 40.26 90 bottom
RC21  51_0402_5%  [R_0402]  117.59 53.41 180 bottom
RC22  33_0402_5%  [R_0402]  168.71 40.25 90 bottom
RC23  33_0402_5%  [R_0402]  166.78 40.25 90 bottom
RC25  1K_0402_5%  [R_0402]  119.72 63.57 0 top
RC26  0_0402_5%  [R0402_0OHM]  191.52 48.52 180 top
RC27  0_0402_5%  [R_0402]  191.52 49.42 180 top
RC29  1K_0402_5%  [R_0402]  201.51 55.18 0 bottom
RC31  1K_0402_5%  [R_0402]  188.77 55.51 180 bottom
RC33  499_0402_1%  [R_0402]  180.58 56.2 180 top
RC34  499_0402_1%  [R_0402]  180.58 57.22 180 top
RC35  0_0402_5%  [R0402_0OHM]  201.46 57.93 270 bottom
RC38  33_0402_5%  [R_0402]  202.43 54.17 180 bottom
RC50  0_0402_5%  [R0402_0OHM]  201.38 64.07 270 bottom
RC55  33_0402_5%  [R_0402]  202.34 61.5 180 bottom
RC61  33_0402_5%  [R_0402]  197.35 59.76 180 top
RC62  33_0402_5%  [R_0402]  192.2 54.68 180 top
RC63  1M_0402_5%  [R_0402]  156.27 77.02 0 bottom
RC65  0_0402_5%  [R0402_0OHM]  155.94 78.04 180 bottom
RC66  10K_0402_5%  [R_0402]  188.71 59.76 180 bottom
RC67  22_0402_5%  [R_0402]  161.12 41.16 270 top
RC68  10K_0402_5%  [R_0402]  188.71 63.82 180 bottom
RC69  3.01K_0402_1%  [R_0402]  158.58 77.03 0 bottom
RC70  22_0402_5%  [R_0402]  160.24 41.16 270 top
RC72  22_0402_5%  [R_0402]  164.64 41.16 270 top
RC74  22_0402_5%  [R_0402]  163.75 41.16 270 top
RC77  0_0402_5%  [R0402_0OHM]  176.77 56.71 180 top
RC78  330K_0402_5%  [R_0402]  169.46 37.86 270 top
RC79  10K_0402_5%  [R_0402]  172.5 36.95 90 top
RC80  8.2K_0402_5%  [R_0402]  177.03 61.28 180 top
RC81  10K_0402_5%  [R_0402]  180.58 54.17 180 top
RC82  10K_0402_5%  [R_0402]  180.58 55.18 180 top
RC87  0_0402_5%  [R0402_0OHM]  184.9 54.17 180 top
RC88  0_0402_5%  [R0402_0OHM]  184.9 55.18 180 top
RC89  0_0402_5%  [R0402_0OHM]  184.9 56.2 180 top
RC91  47K_0402_5%  [R_0402]  185.19 43.16 270 top
RC92  10K_0402_5%  [R_0402]  185.7 50.21 180 bottom
RC95  8.2K_0402_5%  [R_0402]  176.11 62.3 0 top
RC98  0_0402_5%  [R_0402]  111.49 36.64 180 top
RC99  0_0402_5%  [R_0402]  111.49 38.67 180 top
RC102  1K_0402_5%  [R_0402]  89.5 28.26 0 top
RC103  1K_0402_5%  [R_0402]  89.5 27.24 0 top
RC106  1K_0402_5%  [R_0402]  103.62 25.21 180 top
RC109  0_0402_5%  [R_0402]  103.62 36.64 180 top
RC112  0_0402_5%  [R_0402]  89.5 23.18 0 top
RC113  1K_0402_5%  [R_0402]  102.7 22.16 0 top
RC114  49.9_0402_1%  [R_0402]  119.72 61.53 0 top
RC115  0_0402_5%  [R_0402]  110.58 35.63 0 top
RC116  62_0402_5%  [R_0402]  113.63 63.57 0 top
RC117  51_0402_5%  [R_0402]  103.62 23.18 180 top
RC118  0_0402_5%  [R_0402]  110.58 37.66 0 top
RC119  0_0402_5%  [R_0402]  89.5 22.16 0 top
RC120  1K_0402_5%  [R_0402]  90.41 24.2 180 top
RC121  56_0402_5%  [R_0402]  113.63 62.55 0 top
RC122  1K_0402_5%  [R_0402]  175.86 57.72 0 top
RC123  10K_0402_5%  [R_0402]  120.64 62.55 180 top
RC124  51_0402_5%  [R_0402]  116.67 65.6 0 top
RC125  51_0402_5%  [R_0402]  116.67 64.58 0 top
RC126  51_0402_5%  [R_0402]  113.63 61.53 0 bottom
RC127  51_0402_5%  [R_0402]  113.63 62.55 0 bottom
RC128  51_0402_5%  [R_0402]  116.67 60.52 0 top
RC129  51_0402_5%  [R_0402]  116.67 61.53 0 top
RC130  200_0402_1%  [R_0402]  128.05 41.16 270 bottom
RC131  121_0402_1%  [R_0402]  129.07 41.16 270 bottom
RC132  100_0402_1%  [R_0402]  127.04 41.16 270 bottom
RC133  24.9_0402_1%  [R_0402]  156.16 65.9 90 top
RC136  0_0402_5%  [R_0402]  179.67 58.23 0 top
RC139  100K_0402_5%  [R_0402]  169.96 77.99 270 bottom
RC140  1K_0402_5%  [R_0402]  179.92 65.85 0 top
RC141  100K_0402_5%  [R_0402]  170.98 77.99 270 bottom
RC142  100K_0402_5%  [R_0402]  155.99 63.87 90 top
RC149  3.01K_0402_1%  [R_0402]  153.25 75.25 0 bottom
RC152  22.6_0402_1%  [R_0402]  161.07 53.23 270 top
RC153  10K_0402_5%  [R_0402]  183.73 51.63 0 bottom
RC155  100K_0402_5%  [R_0402]  183.98 58.23 0 top
RC156  100K_0402_5%  [R_0402]  179.41 62.55 0 bottom
RC158  100K_0402_5%  [R_0402]  180.33 64.58 180 bottom
RC160  100K_0402_5%  [R_0402]  180.33 63.57 180 bottom
RC161  0_0402_5%  [R0402_0OHM]  120.64 64.58 180 top
RC163  10K_0402_5%  [R_0402]  174.03 77.99 270 bottom
RC164  10K_0402_5%  [R_0402]  174.92 77.99 270 bottom
RC171  10K_0402_5%  [R_0402]  183.98 59.25 0 top
RC174  100K_0402_5%  [R_0402]  183.91 50.21 0 top
RC175  100K_0402_5%  [R_0402]  176.82 41.16 270 top
RC176  1K_0402_5%  [R_0402]  169.96 77.99 270 top
RC178  49.9_0402_1%  [R_0402]  162.04 41.18 270 bottom
RC179  1K_0402_5%  [R_0402]  184.65 52.64 180 bottom
RC180  1K_0402_5%  [R_0402]  180.33 65.6 180 bottom
RC181  1K_0402_5%  [R_0402]  170.98 77.08 90 top
RC183  1K_0402_1%  [R_0402]  117.59 58.49 180 top
RC184  1K_0402_1%  [R_0402]  117.59 57.47 180 bottom
RC185  49.9_0402_1%  [R_0402]  117.59 59.5 180 top
RC186  8.2K_0402_1%  [R_0402]  160.82 77.99 270 bottom
RC187  49.9_0402_1%  [R_0402]  161.14 41.18 270 bottom
RC188  1K_0402_1%  [R_0402]  120.64 55.44 180 top
RC189  1K_0402_1%  [R_0402]  117.59 59.5 180 bottom
RC190  1K_0402_1%  [R_0402]  117.59 58.49 180 bottom
RC191  1K_0402_5%  [R_0402]  120.64 56.45 180 top
RC192  0_0402_5%  [R_0402]  172 77.99 270 bottom
RC193  0_0402_5%  [R_0402]  128.13 76.9 180 bottom
RC194  0_0402_5%  [R_0402]  175.76 40.33 180 bottom
RC195  0_0402_5%  [R_0402]  123.3 41.33 270 bottom
RC196  0_0603_5%  [R_0603]  130.53 77.16 180 bottom
RC197  150_0402_5%  [R_0402]  116.67 61.53 0 bottom
RC198  10K_0402_5%  [R_0402]  117.59 60.52 180 bottom
RC199  10K_0402_5%  [R_0402]  113.63 64.58 0 bottom
RC201  1.5K_0402_5%  [R_0402]  114.54 63.57 180 bottom
RC202  1K_0402_5%  [R_0402]  165.65 41.16 270 top
RC204  75_0402_1%  [R_0402]  119.72 57.47 0 top
RC207  43_0402_5%  [R_0402]  119.72 58.49 0 top
RC208  110_0402_1%  [R_0402]  119.72 59.5 0 top
RC209  100_0402_1%  [R_0402]  117.56 63.1 90 bottom
RC211  5.11_0402_1%  [R_0402]  157.52 58.69 270 top
RC212  0_0402_5%  [R0402_0OHM]  190.03 47.04 90 bottom
RC213  0_0402_5%  [R_0402]  190.97 47.04 90 bottom
RC216  0_0402_5%  [R_0402]  179.87 40.25 90 top
RC217  0_0402_5%  [R0402_0OHM]  178.85 40.25 90 top
RC218  100_0402_1%  [R_0402]  117.56 65.86 270 bottom
RC219  0_0402_5%  [R0402_0OHM]  184.9 57.22 180 top
RC224  0_0402_5%  [R_0402]  201.64 81 0 bottom
RC225  0_0402_5%  [R_0402]  203.16 82.02 0 bottom
RC226  0_0402_5%  [R_0402]  204.06 81.1 0 bottom
RC227  0_0402_5%  [R_0402]  205.92 82.07 0 bottom
RC228  0_0402_5%  [R_0402]  206.88 81.04 0 bottom
RC229  0_0402_5%  [R_0402]  208.31 82.07 0 bottom
RC230  0_0402_5%  [R_0402]  209.46 80.9 0 bottom
RC231  0_0402_5%  [R_0402]  211.72 81.85 180 bottom
RC240  10K_0402_5%  [R_0402]  147.49 74.67 90 bottom
RC241  10K_0402_5%  [R_0402]  148.5 74.67 90 bottom
RC242  10K_0402_5%  [R_0402]  171.49 37.86 270 top
RC243  10K_0402_5%  [R_0402]  170.47 37.86 270 top
RC245  100K_0402_5%  [R_0402]  171.49 40.91 270 top
RC247  10K_0402_5%  [R_0402]  174.41 55.45 270 top
RC300  10K_0402_5%  [R_0402]  171.64 60.33 0 top
RC301  0_0402_5%  [R_0402]  163.97 40.25 90 bottom
RC302  10K_0402_5%  [R_0402]  173.01 62.18 0 top
RC303  10K_0402_5%  [R_0402]  173 61.28 0 top
RC304  100K_0402_5%  [R_0402]  186.96 51.5 0 top
RC305  1K_0402_5%  [R_0402]  103.62 20.63 180 top
RC306  10K_0402_5%  [R_0402]  173.13 77.99 270 bottom
RD2  470_0402_5%  [R_0402]  99.86 3.57 270 top
RD4  1.8K_0402_1%  [R_0402]  89.95 10.78 90 top
RD5  2_0402_1%  [R_0402]  87.92 13.07 90 top
RD6  1.8K_0402_1%  [R_0402]  86.91 13.07 90 top
RD7  24.9_0402_1%  [R_0402]  89.95 13.07 90 top
RD9  220K_0402_5%  [R_0402]  132.88 2.66 90 top
RD10  66.5_0402_1%  [R_0402]  125.77 2.66 90 top
RD11  66.5_0402_1%  [R_0402]  126.78 2.66 90 top
RD12  66.5_0402_1%  [R_0402]  201.97 2.66 90 top
RD13  66.5_0402_1%  [R_0402]  202.98 2.66 90 top
RD14  2M_0402_5%  [R_0402]  133.9 2.66 90 top
RD15  0_0402_5%  [R0402_0OHM]  150.15 11.7 270 top
RD16  0_0402_5%  [R0402_0OHM]  151.17 11.7 270 top
RD18  1.8K_0402_1%  [R_0402]  209.59 3.57 270 top
RD19  2_0402_1%  [R_0402]  208.57 2.66 90 top
RD20  1.8K_0402_1%  [R_0402]  207.56 2.66 90 top
RD21  24.9_0402_1%  [R_0402]  210.6 3.57 270 top
RD22  1.8K_0402_1%  [R_0402]  162.85 10.78 90 top
RD23  2_0402_1%  [R_0402]  161.84 11.7 270 top
RD24  1.8K_0402_1%  [R_0402]  160.82 11.7 270 top
RD25  24.9_0402_1%  [R_0402]  165.65 2.66 90 top
RD27  0_0402_5%  [R0402_0OHM]  221.48 13.78 180 top
RD28  0_0402_5%  [R0402_0OHM]  221.48 14.8 180 top
RE5  100K_0402_5%  [R_0402]  245.07 74.62 0 top
RE8  100K_0402_5%  [R_0402]  258.48 88.03 270 top
RE9  100K_0402_5%  [R_0402]  263.64 77.03 180 top
RE10  100K_0402_5%  [R_0402]  263.64 78.04 180 top
RE11  100K_0402_5%  [R_0402]  253.02 87.9 270 top
RE12  100K_0402_5%  [R_0402]  249.97 70.47 90 top
RE17  100K_0402_5%  [R_0402]  245.07 75.63 0 top
RE20  100K_0402_5%  [R_0402]  250.99 70.47 90 top
RE21  10K_0402_5%  [R_0402]  257.98 70.6 90 top
RE24  10K_0402_5%  [R_0402]  245.99 83 180 top
RE25  100K_0402_5%  [R_0402]  263.26 73.98 180 top
RE26  10_0402_5%  [R_0402]  263.26 72.96 180 top
RE27  33_0402_5%  [R_0402]  245.99 77.66 180 top
RE31  100K_0402_5%  [R_0402]  266.74 52.57 90 top
RE32  0_0402_5%  [R0402_0OHM]  259.12 47.87 90 top
RE33  10K_0402_5%  [R_0402]  266.03 54.42 0 top
RE35  10K_0402_5%  [R_0402]  249.01 62.8 0 top
RE36  100K_0402_5%  [R_0402]  245.45 60.77 0 top
RE37  2.2K_0402_5%  [R_0402]  255.56 47.87 90 top
RE42  10K_0402_5%  [R_0402]  266.74 51.58 270 top
RE43  2.2K_0402_5%  [R_0402]  257.09 47.87 90 top
RE48  10K_0402_5%  [R_0402]  260.13 71.52 270 top
RE51  10K_0402_5%  [R_0402]  261.15 71.52 270 top
RE55  100K_0402_5%  [R_0402]  258.1 68.34 270 top
RE56  10K_0402_5%  [R_0402]  249.01 61.79 0 top
RE57  1K_0402_5%  [R_0402]  260.13 51.58 270 top
RE58  100K_0402_5%  [R_0402]  259.12 51.58 270 top
RE59  0_0402_5%  [R0402_0OHM]  249.92 53.66 180 top
RE60  43_0402_5%  [R_0402]  246.33 55.02 180 top
RE61  0_0402_5%  [R0402_0OHM]  262.67 51.58 270 top
RE62  100K_0402_5%  [R_0402]  267.75 52.47 270 top
RE63  100K_0402_5%  [R_0402]  245.45 57.98 0 top
RE64  4.7K_0402_5%  [R_0402]  258.1 48.78 270 top
RE65  100_0402_1%  [R_0402]  246.37 56.96 180 top
RE66  10_0402_5%  [R_0402]  256.07 67.43 90 top
RE67  10K_0402_5%  [R_0402]  259.12 71.52 270 top
RE68  100K_0402_5%  [R_0402]  263.69 67.43 90 top
RE69  8.2K_0402_5%  [R_0402]  252.26 68.34 270 top
RE70  2.2K_0402_5%  [R_0402]  248.75 69.15 0 top
RE71  49.9_0402_1%  [R_0402]  289.03 35.74 270 bottom
RE72  10K_0402_5%  [R_0402]  289.97 35.73 270 bottom
RE73  10K_0402_5%  [R_0402]  289.08 33.38 180 bottom
RE74  10K_0402_5%  [R_0402]  289.08 32.48 180 bottom
RE75  100K_0402_5%  [R_0402]  290 32.48 90 bottom
RE77  1.58K_0402_1%  [R_0402]  265.72 67.43 90 top
RE78  1K_0402_5%  [R_0402]  257.09 67.43 90 top
RE79  1K_0402_5%  [R_0402]  270.24 59.25 180 top
RE81  10K_0402_5%  [R_0402]  264.71 50.66 90 top
RE82  10K_0402_5%  [R_0402]  263.69 50.66 90 top
RE83  100K_0402_5%  [R_0402]  263.39 76.01 180 top
RE84  100K_0402_5%  [R_0402]  262.72 81.09 0 top
RE85  100K_0402_5%  [R_0402]  262.72 80.08 0 top
RE86  10K_0402_5%  [R_0402]  249.01 60.77 0 top
RE88  47K_0402_5%  [R_0402]  243.26 70.73 0 top
RE274  0_0402_5%  [R_0402]  257.59 90.95 270 top
RE275  0_0402_5%  [R0402_0OHM]  256.58 90.95 270 top
RE276  10K_0402_5%  [R_0402]  259.94 88.03 270 top
RE277  100K_0402_5%  [R_0402]  262.42 70.73 90 top
RE279  0_0402_5%  [R0402_0OHM]  262.65 61.34 0 bottom
RE280  0_0402_5%  [R_0402]  262.65 60.45 0 bottom
RE281  0_0402_5%  [R_0402]  260.3 61.01 180 bottom
RE282  0_0402_5%  [R0402_0OHM]  261.98 58.75 0 bottom
RE283  0_0402_5%  [R_0402]  265.13 54.18 90 top
RI13  10K_0402_5%  [R_0402]  303.26 77.03 180 top
RI14  22.1K_0402_1%  [R_0402]  306.11 82.31 270 top
RL1  10K_0402_5%  [R_0402]  284.98 86.93 180 top
RL2  10K_0402_5%  [R_0402]  284.98 88.46 180 top
RL3  0_0402_5%  [R0402_0OHM]  271.89 87.66 0 top
RL4  4.7K_0402_5%  [R_0402]  275.12 91.05 90 top
RL5  10K_0402_5%  [R_0402]  271.87 89.84 0 top
RL6  4.7K_0402_5%  [R_0402]  271.87 90.74 0 top
RL7  0_0402_5%  [R0402_0OHM]  268.78 91.77 0 top
RL8  0_0603_5%  [R0603_0OHM]  268.29 89.61 0 top
RL9  10K_0402_5%  [R_0402]  269.7 90.76 180 top
RL10  0_0402_5%  [R0402_0OHM]  271.55 83.7 0 top
RL11  1M_0402_5%  [R_0402]  273.53 83.64 270 top
RL12  1K_0402_5%  [R_0402]  284.06 85.41 0 top
RL13  3.01K_0402_1%  [R_0402]  273.29 81.6 180 top
RL14  150_0402_5%  [R_0402]  290.87 103.55 90 top
RL15  75_0402_1%  [R_0402]  297.22 100.09 270 top
RL16  75_0402_1%  [R_0402]  298.49 100.09 270 top
RL17  75_0402_1%  [R_0402]  304.84 100.09 270 top
RL18  75_0402_1%  [R_0402]  306.11 100.09 270 top
RL19  150_0402_5%  [R_0402]  234.86 102.25 270 top
RL20  150_0402_5%  [R_0402]  254.17 98.03 90 top
RL21  2.2_0603_5%  [R_0603]  273.34 80.27 270 top
RL22  2.2_0603_5%  [R_0603]  274.87 80.27 270 top
RL23  2.2_0603_5%  [R_0603]  276.39 80.27 270 top
RL24  2.2_0603_5%  [R_0603]  277.91 80.27 270 top
RL25  2.2_0603_5%  [R_0603]  279.44 80.27 270 top
RL26  2.2_0603_5%  [R_0603]  280.96 80.27 270 top
RL27  2.2_0603_5%  [R_0603]  282.49 80.27 270 top
RL28  2.2_0603_5%  [R_0603]  284.01 80.27 270 top
RL29  1M_0402_5%  [R_0402]  253.71 102.26 180 top
RL30  1M_0402_5%  [R_0402]  236.93 101.16 0 top
RN1  100K_0402_5%  [R_0402]  281.22 63.01 270 top
RN2  100K_0402_5%  [R_0402]  277.91 60.72 270 top
RN3  2.2K_0402_5%  [R_0402]  285.28 62.75 270 top
RN4  2.2K_0402_5%  [R_0402]  287.82 58.08 90 top
RN5  10K_0402_5%  [R_0402]  296.16 37.42 90 bottom
RN6  10K_0402_5%  [R_0402]  304.77 54.83 180 top
RN7  10K_0402_5%  [R_0402]  302.93 54.83 90 top
RN8  4.7K_0402_5%  [R_0402]  297.22 52.69 90 top
RN9  4.7K_0402_5%  [R_0402]  296.2 52.69 90 top
RN10  4.7K_0402_5%  [R_0402]  294.17 53.61 270 top
RN11  4.7K_0402_5%  [R_0402]  295.19 52.69 90 top
RN12  4.7K_0402_5%  [R_0402]  299.45 60.2 0 top
RN13  4.7K_0402_5%  [R_0402]  300.22 61.28 180 top
RN14  4.7K_0402_5%  [R_0402]  297.22 63.26 270 top
RN16  4.7K_0402_5%  [R_0402]  296.2 63.26 270 top
RN18  4.7K_0402_5%  [R_0402]  293.15 52.69 90 top
RN19  7.87K_0402_1%  [R_0402]  292.14 52.69 90 top
RN20  4.7K_0402_5%  [R_0402]  298.23 63.26 270 top
RN21  4.7K_0402_5%  [R_0402]  299.25 63.26 270 top
RN22  4.7K_0402_5%  [R_0402]  299.86 55.03 90 top
RN23  4.7K_0402_5%  [R_0402]  300.77 55.95 270 top
RN24  4.7K_0402_5%  [R_0402]  291.71 60.58 180 top
RN25  4.7K_0402_5%  [R_0402]  290.79 59.68 0 top
RPC1  10K_8P4R_5%  [RP_0804_8P4R]  173.02 39.88 90 top
RPC2  2.2K_0804_8P4R_5%  [RP_0804_8P4R]  165.63 77.47 90 bottom
RPC3  10K_8P4R_5%  [RP_0804_8P4R]  184.76 61.52 180 bottom
RPC4  10K_8P4R_5%  [RP_0804_8P4R]  184.76 64.57 180 bottom
RPC5  10K_8P4R_5%  [RP_0804_8P4R]  180.45 55.43 180 bottom
RPC6  10K_8P4R_5%  [RP_0804_8P4R]  180.95 62.82 180 top
RPC7  10K_8P4R_5%  [RP_0804_8P4R]  188.07 48.31 180 bottom
RPC8  10K_8P4R_5%  [RP_0804_8P4R]  187.68 68.15 0 bottom
RPC9  10K_8P4R_5%  [RP_0804_8P4R]  184.76 58.47 180 bottom
RPC10  10K_8P4R_5%  [RP_0804_8P4R]  184.76 55.43 180 bottom
RPC11  33_0804_8P4R_5%  [RP_0804_8P4R]  187.68 52.91 0 bottom
RPC12  33_0804_8P4R_5%  [RP_0804_8P4R]  187.68 56.97 0 bottom
RPC14  2.2K_0804_8P4R_5%  [RP_0804_8P4R]  179.8 61.27 0 top
RPC15  10K_8P4R_5%  [RP_0804_8P4R]  187.68 65.1 0 bottom
RPC16  10K_8P4R_5%  [RP_0804_8P4R]  180.45 61.27 180 bottom
RPC17  10K_8P4R_5%  [RP_0804_8P4R]  180.45 58.47 180 bottom
RPC18  10K_8P4R_5%  [RP_0804_8P4R]  188.83 62.54 180 bottom
RPC19  10K_8P4R_5%  [RP_0804_8P4R]  187.68 49.86 0 bottom
RPC20  100K_0804_8P4R_5%  [RP_0804_8P4R]  168.68 77.47 90 bottom
RPE2  4.7K_8P4R_5%  [RP_0804_8P4R]  240.51 63.68 0 top
RPE3  2.2K_0804_8P4R_5%  [RP_0804_8P4R]  254.03 51.19 270 top
RPE4  100K_0804_8P4R_5%  [RP_0804_8P4R]  248.84 87.5 90 top
RPE5  100K_0804_8P4R_5%  [RP_0804_8P4R]  266.42 59.24 0 top
RPE6  10K_8P4R_5%  [RP_0804_8P4R]  249.53 56.97 180 top
RPE7  10K_8P4R_5%  [RP_0804_8P4R]  288.63 36.93 0 bottom
RPE8  100K_0804_8P4R_5%  [RP_0804_8P4R]  244.2 79.96 180 top
RPE9  100K_0804_8P4R_5%  [RP_0804_8P4R]  253.9 71.13 270 top
RPE10  100K_0804_8P4R_5%  [RP_0804_8P4R]  269.47 64.57 0 top
RPV1  2.2K_0804_8P4R_5%  [RP_0804_8P4R]  169.39 90.22 0 top
RPV2  2.2K_0804_8P4R_5%  [RP_0804_8P4R]  157.76 102.36 90 bottom
RR1  10_0402_5%  [R_0402]  308.9 68.95 90 top
RR2  191_0402_1%  [R_0402]  303.36 66.36 0 top
RR3  0_0402_5%  [R0402_0OHM]  307.63 68.95 90 top
RR4  0_0402_5%  [R0402_0OHM]  306.62 68.95 90 top
RR5  4.7K_0402_1%  [R_0402]  314.54 60.77 0 top
RR6  100K_0402_5%  [R_0402]  309.41 57.01 90 top
RR8  100K_0402_5%  [R_0402]  308.39 57.93 270 top
RR11  1M_0402_5%  [R_0402]  303.96 57.08 0 top
RR15  10K_0402_5%  [R_0402]  307.12 57.01 90 top
RV1  4.7K_0402_5%  [R_0402]  88.94 98.47 90 top
RV2  4.7K_0402_5%  [R_0402]  90.27 98.38 270 bottom
RV3  100K_0402_5%  [R_0402]  80.3 98.82 270 top
RV4  270K_0402_5%  [R_0402]  91.48 93.36 270 top
RV5  47K_0402_5%  [R_0402]  90.34 93.36 270 top
RV6  47K_0402_5%  [R_0402]  109.44 94.55 90 bottom
RV7  2.2K_0402_5%  [R_0402]  100.93 109.03 0 top
RV8  10K_0402_5%  [R_0402]  103.62 109.08 180 top
RV9  2.2K_0402_5%  [R_0402]  103.44 107.23 90 top
RV10  470_0402_1%  [R_0402]  89.19 105.73 0 top
RV11  470_0402_1%  [R_0402]  88.33 105.73 180 top
RV12  470_0402_1%  [R_0402]  91.24 104.82 180 top
RV13  470_0402_1%  [R_0402]  92.1 104.82 0 top
RV14  470_0402_1%  [R_0402]  86.54 104.84 0 top
RV15  470_0402_1%  [R_0402]  85.68 104.84 180 top
RV16  470_0402_1%  [R_0402]  93.92 105.72 180 top
RV17  470_0402_1%  [R_0402]  94.78 105.72 0 top
RV18  1M_0402_5%  [R_0402]  100.46 98.36 180 top
RV19  10K_0402_5%  [R_0402]  82.87 101.79 180 top
RV20  20K_0402_5%  [R_0402]  100.83 102.92 180 top
RV32  150_0402_1%  [R_0402]  254.22 104.46 0 top
RV33  150_0402_1%  [R_0402]  258.05 104.46 180 top
RV34  150_0402_1%  [R_0402]  260.59 104.46 180 top
RV35  2.2K_0402_5%  [R_0402]  262.93 110.35 90 top
RV36  2.2K_0402_5%  [R_0402]  269.28 110.35 90 top
RV37  1K_0402_5%  [R_0402]  266.23 110.35 90 top
RV38  1K_0402_5%  [R_0402]  263.94 110.35 90 top
RV50  4.99K_0402_1%  [R_0402]  134.15 89.17 270 bottom
RV51  4.7K_0402_5%  [R_0402]  147.69 92.52 180 bottom
RV52  4.7K_0402_5%  [R_0402]  135.17 88.25 90 bottom
RV53  4.7K_0402_5%  [R_0402]  145.33 88.25 90 bottom
RV54  4.7K_0402_5%  [R_0402]  141.14 92.34 270 top
RV55  4.7K_0402_5%  [R_0402]  147.69 96.59 180 bottom
RV56  4.7K_0402_5%  [R_0402]  147.69 95.57 180 bottom
RV57  4.7K_0402_5%  [R_0402]  147.69 94.55 180 bottom
RV58  4.7K_0402_5%  [R_0402]  147.69 93.54 180 bottom
RV60  4.7K_0402_5%  [R_0402]  147.69 91.51 180 bottom
RV61  4.7K_0402_5%  [R_0402]  142.15 91.43 90 top
RV62  4.7K_0402_5%  [R_0402]  149.31 96.59 0 bottom
RV63  4.7K_0402_5%  [R_0402]  149.31 94.55 0 bottom
RV64  4.7K_0402_5%  [R_0402]  149.31 95.57 0 bottom
RV65  4.7K_0402_5%  [R_0402]  149.31 93.54 0 bottom
RV67  1M_0402_5%  [R_0402]  142.19 99.6 270 bottom
RV68  1M_0402_5%  [R_0402]  146.6 103.9 270 bottom
RV69  100K_0402_5%  [R_0402]  132.42 94.55 0 bottom
RV70  100K_0402_5%  [R_0402]  132.42 93.54 0 bottom
RV71  100K_0402_5%  [R_0402]  136.14 95.85 180 top
RV72  100K_0402_5%  [R_0402]  136.14 94.83 180 top
RV73  1M_0402_5%  [R_0402]  157.77 87.39 270 top
RV74  1M_0402_5%  [R_0402]  169 101.16 0 top
RV75  1M_0402_5%  [R_0402]  169.28 93.54 0 top
RV76  150_0402_1%  [R_0402]  160.82 87.39 270 top
RV77  150_0402_1%  [R_0402]  161.84 87.39 270 top
RV78  150_0402_1%  [R_0402]  162.85 87.39 270 top
RV79  100K_0402_5%  [R_0402]  155.21 100.62 180 top
RV80  1M_0402_5%  [R_0402]  152.18 89.17 270 top
RV81  2.2K_0402_5%  [R_0402]  151.17 87.24 90 top
RV82  1M_0402_5%  [R_0402]  169.28 92.52 0 top
